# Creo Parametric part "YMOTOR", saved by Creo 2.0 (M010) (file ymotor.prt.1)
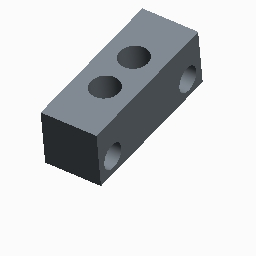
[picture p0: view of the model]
Units: Inch lbm Second (Pro/E Default); INCH, POUND, SECS

Created from: INLBS_PART_SOLID.PRT

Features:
  1. datum plane "RIGHT"
  2. datum plane "TOP"
  3. datum plane "FRONT"
  4. coordinate system
  5. sketch "Sketch 1"
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
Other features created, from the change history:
  extrusion "Extrude 1"
  sketch "Sketch 2"
  extruded cut "Extrude 2"
  sketch "Sketch 3"
  extruded cut "Extrude 3"
  sketch "Sketch 4"
  extruded cut "Extrude 4"
  sketch "Sketch 5"
  extruded cut "Extrude 5"

Surfaces: 16 cylinder, 11 plane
